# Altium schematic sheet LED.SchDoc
size A4
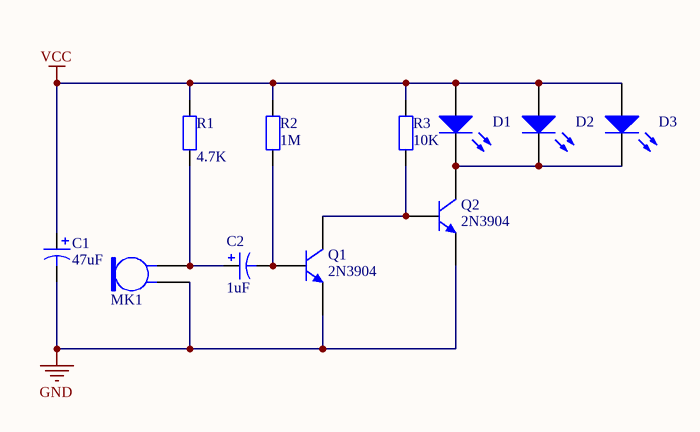
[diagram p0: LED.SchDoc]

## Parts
C1  value 47uF  [RB7.6-15]  (hidden comment: Cap Pol1)
C2  value 1uF  [RB7.6-15]  (hidden comment: Cap Pol1)
D1  LED0  [LED-0]  (value not drawn)
D2  LED0  [LED-0]  (value not drawn)
D3  LED0  [LED-0]  (value not drawn)
MK1  Mic2  [PIN2]  (value not drawn)
Q1  2N3904  [BCY-W3/E4]
Q2  2N3904  [BCY-W3/E4]
R1  value 4.7K  [AXIAL-0.4]  (hidden comment: Res2)
R2  value 1M  [AXIAL-0.4]  (hidden comment: Res2)
R3  value 10K  [AXIAL-0.4]  (hidden comment: Res2)

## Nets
GND: C1.2 MK1.1 Q1.1(E) Q2.1(E)
VCC: C1.1 D1.1(A) D2.1(A) D3.1(A) R1.2 R2.2 R3.2
NetC2_1: C2.1 MK1.2 R1.1
NetC2_2: C2.2 Q1.2(B) R2.1
NetD1_2: D1.2(K) D2.2(K) D3.2(K) Q2.3(C)
NetQ1_3: Q1.3(C) Q2.2(B) R3.1

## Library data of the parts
C1 C2 = Cap Pol1: Polarized Capacitor (Radial)
D1-D3 = LED0: Typical INFRARED GaAs LED
MK1 = Mic2: Microphone
Q1 Q2 = 2N3904: NPN General Purpose Amplifier
R1-R3 = Res2: Resistor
